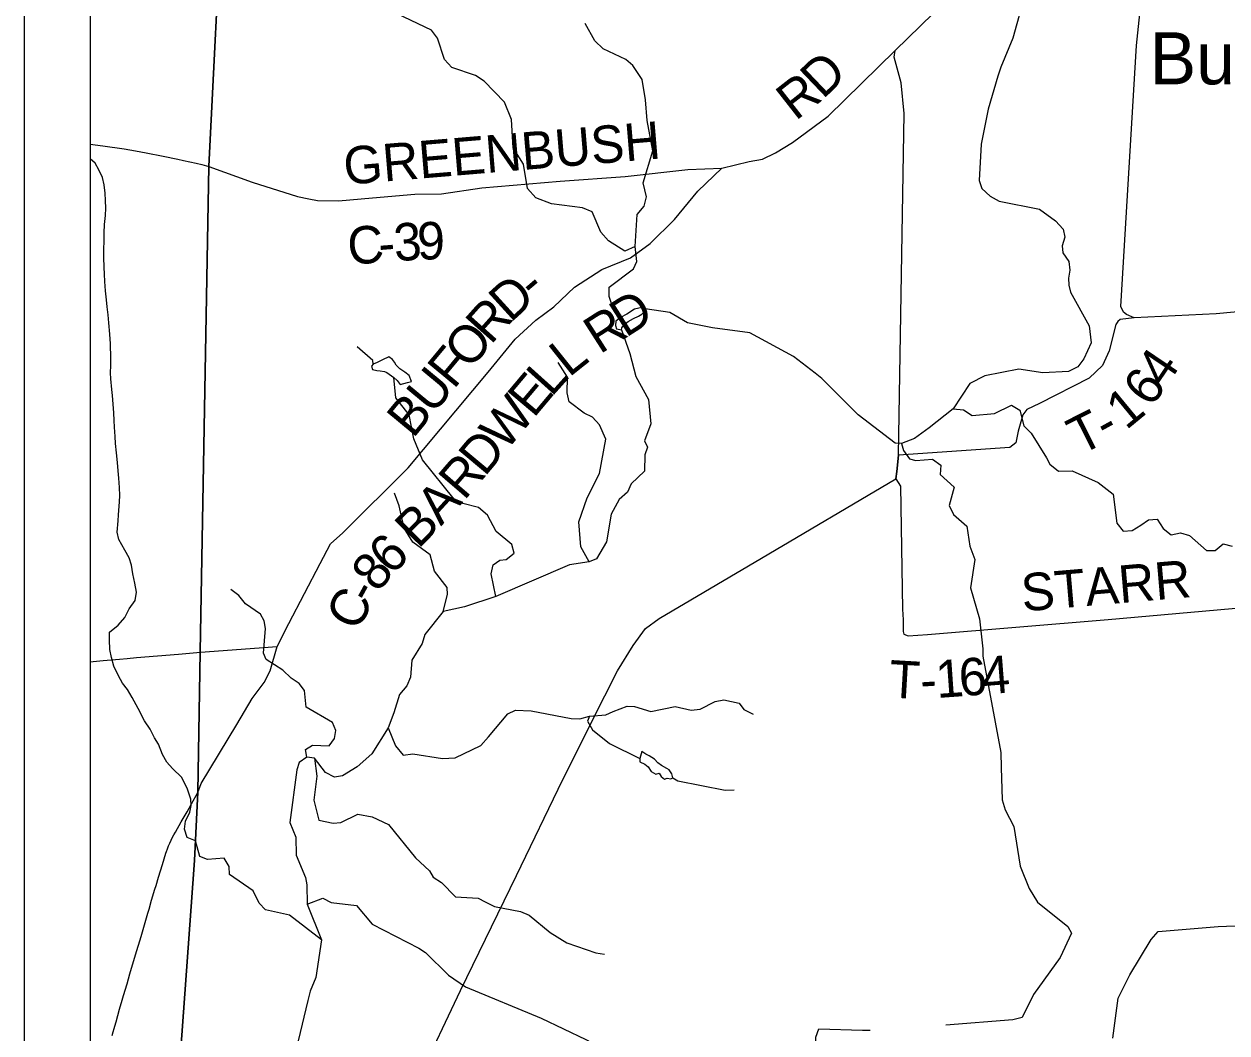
# Model space of a CAD drawing. Extents: x 0 to 34, y 0 to 22.
# Drawn here: x 2 to 3.822, y 16.516 to 18.045 of the extents above; entities that cross this region are included whole.
import ezdxf

# ---------------------------------------------------------------- set-up
doc = ezdxf.new("R2010")
doc.units = 0
for name, color, linetype in [('Default', 7, 'Continuous'), ('GM_X_County_Road', 7, 'Continuous'), ('GM_X_County_Road_Text', 7, 'Continuous'), ('GM_X_Minor_Lake', 7, 'Continuous'), ('GM_X_Minor_River', 7, 'Continuous'), ('GM_X_State_Route', 7, 'Continuous'), ('GM_X_Township_Road', 7, 'Continuous'), ('GM_X_Township_Road_Text', 7, 'Continuous'), ('GM_X_Unincorporated_Text', 7, 'Continuous'), ('SH_Cut_Line', 7, 'Continuous'), ('SH_Data', 7, 'Continuous')]:
    doc.layers.add(name, color=color, linetype=linetype)

msp = doc.modelspace()

# ---------------------------------------------------------------- linework, layer by layer
at = {"layer": 'Default'}
msp.add_lwpolyline([(2.4006, 20.8941), (2.1, 20.8941), (2.1, 14.637), (2.1837, 15.746), (2.258, 16.7775), (2.2632, 16.8811), (2.2668, 17.0936), (2.2797, 17.8302), (2.3212, 18.6531), (2.3791, 20.1601)], close=True, dxfattribs=at)
msp.add_lwpolyline([(2.3212, 18.6531), (2.2797, 17.8302), (2.2668, 17.0936), (2.2632, 16.8811), (2.258, 16.7775), (2.1837, 15.746), (2.1, 14.637), (2.1, 14.4457), (2.4012, 14.4298), (2.4436, 14.4284), (2.5802, 14.4232), (3.783, 14.3901), (4.0144, 14.3862), (4.819, 14.3535), (4.9366, 14.3421), (5.2368, 14.8438), (5.4205, 15.1508), (5.9071, 15.964)], dxfattribs=at)
at = {"layer": 'GM_X_County_Road'}
for points in [[(2.2799, 17.8297), (2.3457, 17.8058), (2.4145, 17.7838), (2.4313, 17.7804), (2.4446, 17.7777), (2.4762, 17.7775), (2.528, 17.7818), (2.592, 17.7876), (2.6324, 17.7878), (2.6933, 17.797), (2.8122, 17.8071), (2.9108, 17.8143), (3.0057, 17.8249), (3.0571, 17.8269), (3.0984, 17.8369), (3.1186, 17.8407), (3.1385, 17.8502), (3.1642, 17.8656), (3.218, 17.9056), (3.3195, 18.0053), (3.4349, 18.1181), (3.5055, 18.1584), (3.6368, 18.2427)], [(3.3246, 17.3921), (3.3335, 17.9099), (3.3286, 17.9564), (3.3183, 17.9953), (3.3195, 18.0053)], [(2.1, 17.8633), (2.1194, 17.8607), (2.1515, 17.8562), (2.1687, 17.8534), (2.1851, 17.8503), (2.2107, 17.8453), (2.2329, 17.8407), (2.2417, 17.8388), (2.2608, 17.8345), (2.2693, 17.8325), (2.2799, 17.8297)], [(2.2634, 16.8806), (2.2684, 16.8939), (2.3222, 16.9834), (2.3456, 17.0231), (2.3639, 17.0474), (2.3729, 17.0651), (2.3833, 17.102), (2.401, 17.1365), (2.4484, 17.2277), (2.4644, 17.2573), (2.4829, 17.274), (2.5817, 17.3726), (2.7033, 17.5178), (2.7439, 17.5675), (2.7752, 17.5965), (2.8025, 17.6168), (2.8337, 17.6466), (2.8752, 17.6731), (2.9188, 17.6909), (2.9487, 17.7128), (2.9854, 17.7489), (3.0207, 17.7919), (3.0571, 17.8269)], [(3.321, 17.3562), (3.3224, 17.367), (3.3246, 17.3921)], [(2.5764, 14.4716), (2.576, 14.4765), (2.5609, 14.9423), (2.3292, 14.9976), (2.3149, 15.0036), (2.301, 15.0111), (2.2909, 15.02), (2.2825, 15.0399), (2.2772, 15.0643), (2.2466, 15.3567), (2.2648, 15.7486), (2.2769, 15.7675), (2.5348, 16.3135), (2.661, 16.5806), (2.7462, 16.7548), (2.8161, 16.9004), (2.88, 17.0272), (2.8992, 17.0651), (2.9226, 17.1033), (2.9413, 17.129), (2.9624, 17.1442), (3.1172, 17.2356), (3.321, 17.3562)], [(2.1337, 16.5119), (2.1351, 16.5177), (2.1364, 16.5227), (2.1374, 16.5261), (2.1394, 16.533), (2.1448, 16.5521), (2.1487, 16.5658), (2.1508, 16.5728), (2.1561, 16.5904), (2.1605, 16.6058), (2.1688, 16.6345), (2.1772, 16.6624), (2.1875, 16.6978), (2.1888, 16.702), (2.1893, 16.7038), (2.1933, 16.7175), (2.1983, 16.7341), (2.2, 16.7395), (2.2038, 16.7523), (2.2095, 16.7716), (2.2147, 16.7883), (2.2157, 16.7913), (2.2171, 16.7953), (2.219, 16.7999), (2.2206, 16.8037), (2.2227, 16.8082), (2.225, 16.8128), (2.2268, 16.8161), (2.2293, 16.8204), (2.2382, 16.8358), (2.2471, 16.8513), (2.2539, 16.8635), (2.2634, 16.8806)]]:
    msp.add_lwpolyline(points, dxfattribs=at)
at = {"layer": 'GM_X_Minor_Lake'}
for points in [[(2.905, 17.582), (2.9058, 17.585), (2.9093, 17.5899), (2.9151, 17.5943), (2.9235, 17.5991), (2.9308, 17.6024), (2.9361, 17.6057), (2.94, 17.6098), (2.9408, 17.6135), (2.9359, 17.6155), (2.9249, 17.6131), (2.913, 17.6057), (2.9034, 17.6006), (2.8965, 17.595), (2.896, 17.5882), (2.8978, 17.5836)], [(2.8978, 17.5836), (2.905, 17.582)], [(2.5603, 17.5096), (2.5651, 17.505), (2.5696, 17.4988), (2.581, 17.502), (2.5871, 17.5034), (2.5834, 17.5126), (2.5767, 17.5176), (2.5692, 17.5227), (2.564, 17.5284), (2.561, 17.5327), (2.558, 17.5369), (2.5524, 17.5411), (2.5432, 17.5364), (2.5348, 17.5323), (2.5287, 17.5298), (2.5264, 17.5268), (2.5278, 17.5215), (2.5346, 17.5202), (2.5396, 17.5198), (2.546, 17.5189), (2.5494, 17.5173)], [(2.5494, 17.5173), (2.5603, 17.5096)], [(2.9327, 16.9269), (2.9406, 16.9237), (2.9454, 16.9195), (2.9499, 16.9122), (2.957, 16.9083), (2.962, 16.9097), (2.9653, 16.9048), (2.9702, 16.9009), (2.9744, 16.9023), (2.98, 16.9011), (2.9831, 16.9029), (2.9813, 16.9086), (2.9772, 16.9148), (2.9738, 16.9167), (2.9656, 16.9214), (2.9603, 16.9257), (2.9551, 16.931), (2.9472, 16.9361), (2.9419, 16.9388), (2.9359, 16.9427), (2.9327, 16.9318)], [(2.9327, 16.9318), (2.9327, 16.9269)]]:
    msp.add_lwpolyline(points, dxfattribs=at)
at = {"layer": 'GM_X_Minor_River'}
for points in [[(3.5224, 18.1114), (3.4978, 18.0239), (3.4796, 17.9799), (3.4752, 17.9664), (3.4604, 17.9166), (3.45, 17.8634), (3.4472, 17.8082), (3.4512, 17.796), (3.4635, 17.7844), (3.4771, 17.777), (3.5383, 17.7646), (3.5627, 17.7471), (3.5742, 17.7344), (3.5767, 17.7222), (3.5727, 17.7091), (3.574, 17.6984), (3.5829, 17.6854), (3.5846, 17.6721), (3.5825, 17.66), (3.5827, 17.6498), (3.5856, 17.6392), (3.6136, 17.5879), (3.6166, 17.5622), (3.6056, 17.5377), (3.5967, 17.5258), (3.5821, 17.5185), (3.5434, 17.5169), (3.5071, 17.522), (3.4558, 17.5123), (3.4328, 17.5006), (3.4075, 17.462), (3.3711, 17.4335), (3.3488, 17.4173), (3.3293, 17.4097), (3.3199, 17.4102), (3.2637, 17.4532), (3.2084, 17.5079), (3.1987, 17.516), (3.1657, 17.5415), (3.0995, 17.5771), (3.0428, 17.5849), (3.0049, 17.5924), (2.9786, 17.6083), (2.9408, 17.6135)], [(2.9256, 17.7084), (2.9103, 17.7011), (2.8856, 17.7167), (2.8736, 17.7298), (2.8608, 17.7607), (2.8458, 17.7666), (2.7992, 17.7727), (2.7751, 17.7818), (2.7628, 17.796), (2.7566, 17.8332), (2.741, 17.8577), (2.7387, 17.9006), (2.7277, 17.9269), (2.6972, 17.9589), (2.684, 17.9674), (2.6482, 17.9794), (2.637, 17.9917), (2.6265, 18.0241), (2.6173, 18.036), (2.5653, 18.0607)], [(2.9034, 17.6006), (2.8941, 17.6094), (2.8865, 17.6326), (2.8863, 17.6463), (2.9232, 17.6744), (2.9283, 17.6853), (2.9256, 17.7084), (2.9287, 17.7568), (2.9395, 17.7695), (2.9431, 17.7835), (2.9378, 17.8048), (2.9526, 17.853), (2.9439, 17.8993), (2.9417, 17.9304), (2.9365, 17.9612), (2.9225, 17.9826), (2.9116, 17.9919), (2.8774, 18.0077), (2.8647, 18.02), (2.8499, 18.046)], [(2.2598, 16.8073), (2.247, 16.8125), (2.2429, 16.8247), (2.2446, 16.8368), (2.2512, 16.8507), (2.2532, 16.8609), (2.2529, 16.8703), (2.2478, 16.8855), (2.2389, 16.9031), (2.2251, 16.9169), (2.2161, 16.9265), (2.2098, 16.9379), (2.2036, 16.9539), (2.1977, 16.9634), (2.191, 16.9763), (2.1824, 16.9893), (2.1728, 17.0076), (2.1639, 17.0244), (2.1565, 17.0366), (2.149, 17.0461), (2.1431, 17.0576), (2.1361, 17.072), (2.1325, 17.0853), (2.13, 17.0974), (2.1294, 17.1118), (2.1295, 17.1236), (2.1425, 17.1344), (2.1525, 17.1459), (2.159, 17.1587), (2.1683, 17.1715), (2.1703, 17.1843), (2.1678, 17.1979), (2.165, 17.212), (2.1628, 17.2252), (2.1592, 17.2363), (2.1525, 17.2481), (2.1436, 17.2641), (2.1411, 17.2751), (2.1424, 17.2921), (2.1433, 17.3015), (2.1446, 17.3212), (2.1451, 17.3306), (2.1445, 17.3427), (2.1435, 17.3571), (2.1425, 17.3681), (2.1416, 17.381), (2.1402, 17.3954), (2.1385, 17.4094), (2.1378, 17.4204), (2.1372, 17.4344), (2.1366, 17.4446), (2.136, 17.456), (2.135, 17.4692), (2.134, 17.4821), (2.133, 17.4916), (2.1313, 17.5075), (2.131, 17.5169), (2.1315, 17.5279), (2.1313, 17.5389), (2.1311, 17.5604), (2.1302, 17.5752), (2.1285, 17.5926), (2.1275, 17.6048), (2.1261, 17.6165), (2.1247, 17.6275), (2.1234, 17.6411), (2.1224, 17.6552), (2.1218, 17.6661), (2.1215, 17.6771), (2.121, 17.6915), (2.1214, 17.729), (2.1219, 17.7415), (2.1232, 17.7551), (2.1237, 17.7664), (2.1235, 17.7778), (2.1229, 17.7888), (2.1215, 17.8016), (2.1186, 17.8127), (2.1135, 17.8245), (2.1079, 17.8344), (2.1, 17.8409)], [(2.905, 17.582), (2.9177, 17.5462), (2.9267, 17.5112), (2.9458, 17.4761), (2.9498, 17.4393), (2.9399, 17.4137), (2.9443, 17.4042), (2.9403, 17.3922), (2.94, 17.3676), (2.9199, 17.3486), (2.914, 17.3359), (2.9017, 17.3247), (2.8896, 17.3026), (2.8825, 17.2607), (2.8673, 17.2345), (2.8559, 17.2302), (2.8266, 17.2258), (2.7147, 17.1778), (2.6675, 17.1619), (2.6351, 17.1549), (2.6073, 17.1202), (2.6029, 17.1063), (2.5873, 17.0809), (2.5854, 17.0552), (2.5799, 17.042), (2.5687, 17.029), (2.5603, 17.0015), (2.5516, 16.9786), (2.5267, 16.9393), (2.5048, 16.9196), (2.4826, 16.906), (2.4704, 16.9039), (2.4569, 16.911), (2.4401, 16.9324), (2.4284, 16.9342), (2.4169, 16.926), (2.4133, 16.9151), (2.4026, 16.8351), (2.4117, 16.8126), (2.4124, 16.7857), (2.4266, 16.7518), (2.4284, 16.7404), (2.4287, 16.7112), (2.4505, 16.6571), (2.442, 16.6001), (2.4334, 16.5794), (2.4297, 16.565), (2.4151, 16.5043)], [(2.5287, 17.5298), (2.5284, 17.5355), (2.5045, 17.556)], [(2.8559, 17.2302), (2.8437, 17.2531), (2.8405, 17.2906), (2.8532, 17.3271), (2.8716, 17.3642), (2.8812, 17.4159), (2.872, 17.438), (2.8612, 17.4495), (2.8484, 17.4554), (2.8259, 17.4728), (2.8227, 17.4865), (2.8231, 17.51), (2.8094, 17.5322)], [(2.7147, 17.1778), (2.7077, 17.2119), (2.7109, 17.2255), (2.7209, 17.2329), (2.7304, 17.2339), (2.7427, 17.2431), (2.7391, 17.2564), (2.7151, 17.2761), (2.7023, 17.3009), (2.6884, 17.3125), (2.6646, 17.3186), (2.6514, 17.3253), (2.6038, 17.3847), (2.5903, 17.4164), (2.5836, 17.4528), (2.5632, 17.4789), (2.5603, 17.5096)], [(3.4075, 17.462), (3.4231, 17.4606), (3.4366, 17.4521), (3.4704, 17.4549), (3.496, 17.4677), (3.5084, 17.4603), (3.5148, 17.4363), (3.526, 17.4252), (3.549, 17.3877), (3.5541, 17.3781), (3.5672, 17.3677), (3.5881, 17.3681), (3.6272, 17.3504), (3.6501, 17.3326), (3.6555, 17.2886), (3.6651, 17.2767), (3.6788, 17.2779), (3.6918, 17.2856), (3.7037, 17.2938), (3.7166, 17.2947), (3.7259, 17.2805), (3.7379, 17.2712), (3.7519, 17.274), (3.7655, 17.27), (3.7913, 17.2472), (3.8046, 17.2473), (3.8165, 17.2577), (3.8301, 17.2541)], [(3.3293, 17.4097), (3.3322, 17.399), (3.3415, 17.3864), (3.3513, 17.3839), (3.3764, 17.3858), (3.3887, 17.3768), (3.3881, 17.3628), (3.4091, 17.3436), (3.4014, 17.3157), (3.408, 17.3019), (3.4282, 17.2842), (3.4331, 17.2538), (3.4403, 17.2336), (3.434, 17.191), (3.4476, 17.1438), (3.4526, 17.0983), (3.4528, 17.087), (3.4797, 16.9411), (3.4805, 16.9184), (3.482, 16.8692), (3.4863, 16.8543), (3.4995, 16.8291), (3.5092, 16.7688), (3.5227, 16.7352), (3.5352, 16.7145), (3.5813, 16.6774), (3.5868, 16.6671), (3.5699, 16.6306), (3.5292, 16.5745), (3.5119, 16.5392), (3.4978, 16.5357), (3.3965, 16.5277)], [(2.6351, 17.1549), (2.6416, 17.1805), (2.641, 17.1915), (2.622, 17.2161), (2.6152, 17.2408), (2.589, 17.2598), (2.5757, 17.2812), (2.5682, 17.315), (2.5613, 17.3344)], [(2.4284, 16.9342), (2.4263, 16.9455), (2.437, 16.9522), (2.462, 16.9514), (2.4702, 16.9622), (2.4723, 16.9743), (2.4675, 16.9864), (2.4273, 17.0098), (2.4247, 17.0349), (2.4169, 17.0456), (2.4045, 17.0538), (2.3918, 17.0661), (2.367, 17.082), (2.363, 17.0919), (2.3658, 17.1289), (2.3637, 17.1407), (2.3582, 17.1506), (2.3353, 17.1665), (2.3253, 17.1792), (2.3133, 17.1881)], [(2.5516, 16.9786), (2.5629, 16.9511), (2.5744, 16.9369), (2.5889, 16.9389), (2.6339, 16.9321), (2.6533, 16.9333), (2.6922, 16.9519), (2.7034, 16.9649), (2.7328, 17), (2.7447, 17.0051), (2.7682, 17.0043), (2.829, 16.9927), (2.8419, 16.992), (2.8564, 16.9963), (2.8814, 16.9982), (2.8925, 17.0033), (2.9139, 17.0116), (2.9249, 17.011), (2.9494, 17.0034), (2.9863, 17.0107), (3.0109, 17.0054), (3.0242, 17.0067), (3.0471, 17.0187), (3.06, 17.0208), (3.0835, 17.0158), (3.0905, 17.0063), (3.1044, 16.9992)], [(2.8564, 16.9963), (2.8536, 16.9884), (2.8614, 16.9754), (2.8868, 16.9546), (2.9327, 16.9318)], [(2.4401, 16.9324), (2.4435, 16.9051), (2.4391, 16.8689), (2.4466, 16.8385), (2.4682, 16.8339), (2.4799, 16.8349), (2.5059, 16.8477), (2.5275, 16.8435), (2.5523, 16.8321), (2.5932, 16.7814), (2.6142, 16.7618), (2.6197, 16.7522), (2.6325, 16.744), (2.6537, 16.7224), (2.6878, 16.7203), (2.6987, 16.7149), (2.7127, 16.7078), (2.752, 16.7003), (2.7652, 16.6944), (2.797, 16.6681), (2.8221, 16.6525), (2.8662, 16.6373), (2.8795, 16.6356)], [(2.9831, 16.9029), (2.9906, 16.8983), (3.0624, 16.8838), (3.0757, 16.8847)], [(2.4505, 16.6571), (2.4022, 16.6943), (2.3656, 16.7025), (2.3562, 16.7125), (2.3471, 16.7316), (2.311, 16.756), (2.3105, 16.7685), (2.3031, 16.7808), (2.2777, 16.7789), (2.2664, 16.7837), (2.2598, 16.8073)], [(2.4287, 16.7112), (2.4527, 16.7203), (2.4655, 16.714), (2.5037, 16.7092), (2.5275, 16.6811), (2.5979, 16.6447), (2.6084, 16.6381), (2.6431, 16.6034), (2.669, 16.5859), (2.7835, 16.5384), (2.8512, 16.5062), (2.9373, 16.4604), (2.9483, 16.4564), (2.9702, 16.4545), (3.1446, 16.4529), (3.1564, 16.4524), (3.1928, 16.4525), (3.1983, 16.466), (3.1998, 16.5095), (3.2042, 16.5223), (3.2701, 16.5204), (3.2818, 16.5202)], [(3.6494, 16.508), (3.6576, 16.5685), (3.6752, 16.6041), (3.7076, 16.6577), (3.718, 16.6696), (3.8091, 16.6775), (3.8216, 16.678), (3.9263, 16.6803)]]:
    msp.add_lwpolyline(points, dxfattribs=at)
at = {"layer": 'GM_X_State_Route'}
msp.add_lwpolyline([(3.8548, 17.6108), (3.8061, 17.6061), (3.6818, 17.6001), (3.6702, 17.605), (3.6657, 17.6085), (3.6618, 17.6173), (3.6853, 18.0131), (3.6991, 18.1432)], dxfattribs=at)
at = {"layer": 'GM_X_Township_Road'}
msp.add_line((2.2671, 17.0931), (2.3833, 17.102), dxfattribs=at)
for points in [[(3.6818, 17.6001), (3.6606, 17.5976), (3.6572, 17.5947), (3.6541, 17.5898), (3.6439, 17.5498), (3.6337, 17.5276), (3.6136, 17.5086), (3.5382, 17.4702), (3.519, 17.4611), (3.5132, 17.4528), (3.506, 17.428), (3.5027, 17.4106), (3.4934, 17.4036), (3.3246, 17.3921)], [(3.3246, 17.3921), (3.3224, 17.367), (3.321, 17.3562)], [(3.321, 17.3562), (3.3276, 17.3451), (3.3311, 17.1583), (3.332, 17.1424), (3.3318, 17.1307), (3.3317, 17.1246), (3.3328, 17.1204), (3.3392, 17.118), (3.3689, 17.1198), (3.6423, 17.1426), (3.9554, 17.1704)], [(2.1, 17.0787), (2.1047, 17.0791), (2.1201, 17.0805), (2.1444, 17.0825), (2.1562, 17.0836), (2.1702, 17.085), (2.2339, 17.0904), (2.2671, 17.0931)]]:
    msp.add_lwpolyline(points, dxfattribs=at)
at = {"layer": 'SH_Cut_Line'}
msp.add_lwpolyline([(2.4006, 20.8941), (2.1, 20.8941), (2.1, 14.637), (2.1837, 15.746), (2.258, 16.7775), (2.2632, 16.8811), (2.2668, 17.0936), (2.2797, 17.8302), (2.3212, 18.6531), (2.3791, 20.1601)], close=True, dxfattribs=at)
msp.add_lwpolyline([(2.3212, 18.6531), (2.2797, 17.8302), (2.2668, 17.0936), (2.2632, 16.8811), (2.258, 16.7775), (2.1837, 15.746), (2.1, 14.637), (2.1, 14.4457), (2.4012, 14.4298), (2.4436, 14.4284), (2.5802, 14.4232), (3.783, 14.3901), (4.0144, 14.3862), (4.819, 14.3535), (4.9366, 14.3421), (5.0616, 14.3309), (5.4793, 14.3187), (6.7418, 14.3069), (6.8864, 14.3056), (7.3204, 14.3032), (8.6074, 14.2911), (8.7041, 14.2905), (8.9, 14.2922), (8.9, 20.8941)], dxfattribs=at)
at = {"layer": 'SH_Data'}
for p, q in [((2, 21), (2, 14)), ((2.1, 20.9), (2.1, 14.1))]:
    msp.add_line(p, q, dxfattribs=at)

# ---------------------------------------------------------------- texts
at = {"layer": 'GM_X_County_Road_Text'}
for s, height, rotation, p in [('D', 0.0568, 43.6686, (3.21, 17.9303)), ('R', 0.0568, 38.0204, (3.1687, 17.8977)), ('GREENBUSH', 0.05682, 4.7824, (2.4864, 17.8016)), ('C', 0.0568, 4.8102, (2.4923, 17.6801)), ('3', 0.0568, 3.7756, (2.5618, 17.6858)), ('9', 0.0568, 1.2959, (2.596, 17.6881)), ('-', 0.0568, 4.5713, (2.5387, 17.684)), ('D', 0.0568, 42.2486, (2.7369, 17.5917)), ('-', 0.0568, 40.4167, (2.7736, 17.625)), ('R', 0.0568, 48.2846, (2.707, 17.558)), ('D', 0.0568, 32.4831, (2.9114, 17.5692)), ('R', 0.0568, 32.6362, (2.8722, 17.5441)), ('O', 0.0568, 50.2628, (2.6754, 17.52)), ('F', 0.0568, 50.3373, (2.6509, 17.4905)), ('L', 0.0568, 38.5507, (2.8255, 17.5089)), ('U', 0.0568, 50.3364, (2.619, 17.452)), ('E', 0.0568, 49.9373, (2.7719, 17.4469)), ('L', 0.0568, 48.069, (2.7989, 17.479)), ('B', 0.0568, 50.3376, (2.5892, 17.416)), ('W', 0.0568, 50.1663, (2.7298, 17.3964)), ('D', 0.0568, 50.1068, (2.6977, 17.358)), ('R', 0.0568, 49.2892, (2.6667, 17.3219)), ('A', 0.0568, 47.5312, (2.6316, 17.2836)), ('B', 0.0568, 45.296, (2.5971, 17.2487)), ('6', 0.0568, 44.9025, (2.5567, 17.2084)), ('8', 0.0568, 51.8561, (2.5363, 17.1822)), ('C', 0.0568, 62.0664, (2.5048, 17.1227)), ('-', 0.0568, 61.443, (2.5266, 17.1638))]:
    msp.add_text(s, height=height, rotation=rotation, dxfattribs=at).set_placement(p)
at = {"layer": 'GM_X_Township_Road_Text'}
for s, height, rotation, p in [('4', 0.0568, 56.0293, (3.7291, 17.4928)), ('6', 0.0568, 54.2269, (3.7075, 17.4628)), ('1', 0.0568, 39.4837, (3.6696, 17.429)), ('T', 0.0568, 26.7625, (3.5998, 17.3911)), ('-', 0.0568, 28.8953, (3.6397, 17.4113)), ('STARR', 0.05682, 4.887, (3.5131, 17.1549)), ('T', 0.0568, 356.6639, (3.3093, 17.0247)), ('1', 0.0568, 4.0422, (3.383, 17.0237)), ('6', 0.0568, 4.4127, (3.4183, 17.0262)), ('4', 0.0568, 4.5152, (3.4533, 17.0289)), ('-', 0.0568, 3.4662, (3.3591, 17.0223))]:
    msp.add_text(s, height=height, rotation=rotation, dxfattribs=at).set_placement(p)
at = {"layer": 'GM_X_Unincorporated_Text'}
msp.add_text('Buford', height=0.07898, rotation=0, dxfattribs=at).set_placement((3.7053, 17.954))

doc.saveas('drawing.dxf')
